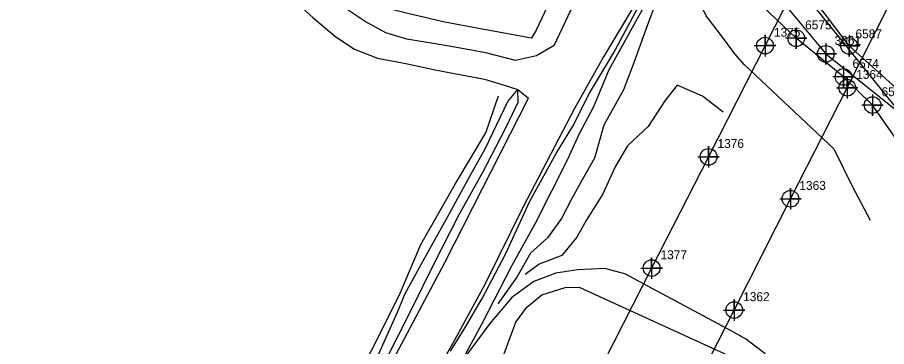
# Model space of a CAD drawing. Extents: x 2062781 to 2066835, y 358981 to 366501.
# Drawn here: x 2065489 to 2065733, y 364608.5 to 364700.9 of the extents above; entities that cross this region are included whole.
import ezdxf

# ---------------------------------------------------------------- set-up
doc = ezdxf.new("R2010")
doc.units = 0
for name, color, linetype in [('Exist DTM Breakline Underwater Cogo Number', 7, 'Continuous'), ('Exist DTM Drainline', 7, 'Continuous'), ('Exist DTM Regular Point Underwater Cogo Number', 7, 'Continuous'), ('Exist DTM Ridgeline', 7, 'Continuous'), ('Exist DTM Ridgeline Cogo Number', 7, 'Continuous'), ('Exist DTM Ridgeline Cogo Point CELL', 7, 'Continuous'), ('Exist Structure Major Deck Tunnel Box Culvert', 7, 'Continuous'), ('Exist Structure Major Deck Tunnel Box Culvert Cogo Number', 7, 'Continuous'), ('Exist Structure Major Deck Tunnel Box Culvert Cogo Point CELL', 7, 'Continuous'), ('PH Exist DTM Breakline', 7, 'Continuous'), ('PH Exist DTM Point', 7, 'Continuous')]:
    doc.layers.add(name, color=color, linetype=linetype)

msp = doc.modelspace()

# ---------------------------------------------------------------- linework, layer by layer
at = {"layer": 'Exist DTM Breakline Underwater Cogo Number'}
msp.add_lwpolyline([(2065715.94, 364693.69), (2065715.94, 364687.69), (2065715.94, 364690.69), (2065718.94, 364690.69), (2065712.94, 364690.69)], dxfattribs=at)
msp.add_lwpolyline([(2065715.94, 364693.69), (2065715.94, 364687.69), (2065715.94, 364690.69), (2065718.94, 364690.69), (2065712.94, 364690.69)], dxfattribs=at)
msp.add_lwpolyline([(2065715.94, 364693.69), (2065715.94, 364687.69), (2065715.94, 364690.69), (2065718.94, 364690.69), (2065712.94, 364690.69)], dxfattribs=at)
msp.add_circle((2065715.94, 364690.69), 2.34, dxfattribs=at)
msp.add_circle((2065715.94, 364690.69), 2.34, dxfattribs=at)
msp.add_circle((2065715.94, 364690.69), 2.34, dxfattribs=at)
at = {"layer": 'Exist DTM Drainline'}
for p in [(2065704.09, 364714.74), (2065715.94, 364690.69)]:
    msp.add_line(p, (2065736.94, 364673.9), dxfattribs=at)
msp.add_lwpolyline([(2065684.56, 364732.28), (2065688.06, 364722.81), (2065697.32, 364709.2), (2065704.32, 364704.74), (2065715.94, 364690.69)], dxfattribs=at)
at = {"layer": 'Exist DTM Ridgeline'}
for points in [[(2065756.36, 364640.41), (2065752.93, 364643.32), (2065750.15, 364650.41), (2065736.13, 364666.27), (2065729.12, 364676.31), (2065720.96, 364684.21), (2065707.66, 364695.07), (2065692.58, 364709.52), (2065685.05, 364722.21), (2065679.07, 364731.03), (2065683.91, 364739.54), (2065689.64, 364738.67), (2065696, 364731.44), (2065702.13, 364731.15), (2065704.47, 364727.59), (2065700.39, 364723.94)], [(2065722.51, 364692.9), (2065711.1, 364708.1), (2065707.56, 364711.6), (2065700.39, 364723.94)], [(2065722.51, 364692.9), (2065736.53, 364680.31), (2065745.83, 364668.65), (2065755.91, 364658.15), (2065762.12, 364648.29)]]:
    msp.add_lwpolyline(points, dxfattribs=at)
at = {"layer": 'Exist DTM Ridgeline Cogo Point CELL'}
for points in [[(2065707.66, 364698.07), (2065707.66, 364692.07), (2065707.66, 364695.07), (2065710.66, 364695.07), (2065704.66, 364695.07)], [(2065707.66, 364698.07), (2065707.66, 364692.07), (2065707.66, 364695.07), (2065710.66, 364695.07), (2065704.66, 364695.07)], [(2065707.66, 364698.07), (2065707.66, 364692.07), (2065707.66, 364695.07), (2065710.66, 364695.07), (2065704.66, 364695.07)], [(2065722.51, 364695.9), (2065722.51, 364689.9), (2065722.51, 364692.9), (2065725.51, 364692.9), (2065719.51, 364692.9)], [(2065722.51, 364695.9), (2065722.51, 364689.9), (2065722.51, 364692.9), (2065725.51, 364692.9), (2065719.51, 364692.9)], [(2065722.51, 364695.9), (2065722.51, 364689.9), (2065722.51, 364692.9), (2065725.51, 364692.9), (2065719.51, 364692.9)], [(2065720.96, 364687.21), (2065720.96, 364681.21), (2065720.96, 364684.21), (2065723.96, 364684.21), (2065717.96, 364684.21)], [(2065720.96, 364687.21), (2065720.96, 364681.21), (2065720.96, 364684.21), (2065723.96, 364684.21), (2065717.96, 364684.21)], [(2065720.96, 364687.21), (2065720.96, 364681.21), (2065720.96, 364684.21), (2065723.96, 364684.21), (2065717.96, 364684.21)], [(2065729.12, 364679.31), (2065729.12, 364673.31), (2065729.12, 364676.31), (2065732.12, 364676.31), (2065726.12, 364676.31)], [(2065729.12, 364679.31), (2065729.12, 364673.31), (2065729.12, 364676.31), (2065732.12, 364676.31), (2065726.12, 364676.31)], [(2065729.12, 364679.31), (2065729.12, 364673.31), (2065729.12, 364676.31), (2065732.12, 364676.31), (2065726.12, 364676.31)]]:
    msp.add_lwpolyline(points, dxfattribs=at)
for centre in [(2065707.66, 364695.07), (2065707.66, 364695.07), (2065707.66, 364695.07), (2065722.51, 364692.9), (2065722.51, 364692.9), (2065722.51, 364692.9), (2065720.96, 364684.21), (2065720.96, 364684.21), (2065720.96, 364684.21), (2065729.12, 364676.31), (2065729.12, 364676.31), (2065729.12, 364676.31)]:
    msp.add_circle(centre, 2.34, dxfattribs=at)
at = {"layer": 'Exist Structure Major Deck Tunnel Box Culvert'}
msp.add_lwpolyline([(2065674.29, 364587.57), (2065690.26, 364618.75), (2065706.04, 364650), (2065722, 364681.17), (2065737.82, 364712.48), (2065753.7, 364743.62), (2065769.52, 364774.84), (2065785.48, 364805.99), (2065801.23, 364837.35), (2065778.26, 364849.13), (2065762.32, 364817.83), (2065746.45, 364786.64), (2065730.62, 364755.39), (2065714.76, 364724.23), (2065698.9, 364692.99), (2065683.06, 364661.76), (2065667.07, 364630.54), (2065651.24, 364599.44), (2065674.29, 364587.57)], dxfattribs=at)
at = {"layer": 'Exist Structure Major Deck Tunnel Box Culvert Cogo Point CELL'}
for points in [[(2065695.9, 364692.99), (2065701.9, 364692.99), (2065698.9, 364692.99), (2065698.9, 364695.99), (2065698.9, 364689.99)], [(2065695.9, 364692.99), (2065701.9, 364692.99), (2065698.9, 364692.99), (2065698.9, 364695.99), (2065698.9, 364689.99)], [(2065695.9, 364692.99), (2065701.9, 364692.99), (2065698.9, 364692.99), (2065698.9, 364695.99), (2065698.9, 364689.99)], [(2065719, 364681.17), (2065725, 364681.17), (2065722, 364681.17), (2065722, 364684.17), (2065722, 364678.17)], [(2065719, 364681.17), (2065725, 364681.17), (2065722, 364681.17), (2065722, 364684.17), (2065722, 364678.17)], [(2065719, 364681.17), (2065725, 364681.17), (2065722, 364681.17), (2065722, 364684.17), (2065722, 364678.17)], [(2065680.06, 364661.76), (2065686.06, 364661.76), (2065683.06, 364661.76), (2065683.06, 364664.76), (2065683.06, 364658.76)], [(2065680.06, 364661.76), (2065686.06, 364661.76), (2065683.06, 364661.76), (2065683.06, 364664.76), (2065683.06, 364658.76)], [(2065680.06, 364661.76), (2065686.06, 364661.76), (2065683.06, 364661.76), (2065683.06, 364664.76), (2065683.06, 364658.76)], [(2065703.04, 364650), (2065709.04, 364650), (2065706.04, 364650), (2065706.04, 364653), (2065706.04, 364647)], [(2065703.04, 364650), (2065709.04, 364650), (2065706.04, 364650), (2065706.04, 364653), (2065706.04, 364647)], [(2065703.04, 364650), (2065709.04, 364650), (2065706.04, 364650), (2065706.04, 364653), (2065706.04, 364647)], [(2065664.07, 364630.54), (2065670.07, 364630.54), (2065667.07, 364630.54), (2065667.07, 364633.54), (2065667.07, 364627.54)], [(2065664.07, 364630.54), (2065670.07, 364630.54), (2065667.07, 364630.54), (2065667.07, 364633.54), (2065667.07, 364627.54)], [(2065664.07, 364630.54), (2065670.07, 364630.54), (2065667.07, 364630.54), (2065667.07, 364633.54), (2065667.07, 364627.54)], [(2065687.26, 364618.75), (2065693.26, 364618.75), (2065690.26, 364618.75), (2065690.26, 364621.75), (2065690.26, 364615.75)], [(2065687.26, 364618.75), (2065693.26, 364618.75), (2065690.26, 364618.75), (2065690.26, 364621.75), (2065690.26, 364615.75)], [(2065687.26, 364618.75), (2065693.26, 364618.75), (2065690.26, 364618.75), (2065690.26, 364621.75), (2065690.26, 364615.75)]]:
    msp.add_lwpolyline(points, dxfattribs=at)
for centre in [(2065698.9, 364692.99), (2065698.9, 364692.99), (2065698.9, 364692.99), (2065722, 364681.17), (2065722, 364681.17), (2065722, 364681.17), (2065683.06, 364661.76), (2065683.06, 364661.76), (2065683.06, 364661.76), (2065706.04, 364650), (2065706.04, 364650), (2065706.04, 364650), (2065667.07, 364630.54), (2065667.07, 364630.54), (2065667.07, 364630.54), (2065690.26, 364618.75), (2065690.26, 364618.75), (2065690.26, 364618.75)]:
    msp.add_circle(centre, 2.34, dxfattribs=at)
at = {"layer": 'PH Exist DTM Breakline'}
for points in [[(2065660.05, 364747.21), (2065652.74, 364733.94), (2065647.3, 364724.19), (2065634.61, 364697.38), (2065633.33, 364695.06), (2065619.03, 364697.74), (2065609.03, 364699.54), (2065598.94, 364701.96), (2065587.11, 364704.96), (2065580.61, 364708.55), (2065571.79, 364715.59), (2065559.5, 364725.9), (2065541.44, 364743.3), (2065532.03, 364751.24), (2065520.5, 364760.95), (2065511.71, 364768.87), (2065500.52, 364779), (2065493.11, 364785.37), (2065487.24, 364790.19), (2065477.93, 364797.52), (2065465.26, 364806.84), (2065452.16, 364818.79)], [(2065639.68, 364693), (2065634.69, 364690.12), (2065628.85, 364688.84), (2065620.9, 364690.85), (2065617.44, 364691.57), (2065610.73, 364692.79), (2065598.28, 364694.84), (2065592.41, 364696.62), (2065586.64, 364699.8), (2065575.14, 364707.52), (2065561.85, 364718.71), (2065546.86, 364732.09), (2065527.94, 364749.68), (2065508.21, 364767.32), (2065489.17, 364783.14), (2065470.41, 364798.67), (2065451.42, 364814.97)], [(2065447.48, 364808.89), (2065476.57, 364784.85), (2065501.56, 364763.78), (2065522.61, 364745.31), (2065540.38, 364728.8), (2065555.41, 364715.91), (2065571.89, 364700.89), (2065578.36, 364695.51), (2065583.64, 364691.99), (2065590.04, 364689.44), (2065598.02, 364687.96), (2065606.75, 364686.07), (2065620.11, 364683.54), (2065625.38, 364681.99), (2065629.46, 364680.72), (2065632.47, 364678.22)], [(2065639.68, 364693), (2065645.18, 364704.75), (2065652.35, 364720.03), (2065665.17, 364744.65), (2065672.12, 364758.01)], [(2065678.72, 364737.58), (2065673.92, 364728.12), (2065662.86, 364705.32), (2065653.55, 364689.83), (2065645.39, 364675.34), (2065631.03, 364647.71), (2065620.21, 364625.92), (2065611.7, 364610.32), (2065595.23, 364580.8), (2065582.27, 364556.74), (2065569.58, 364532.46), (2065556.01, 364505), (2065544.12, 364483.42), (2065531.2, 364457.8), (2065510.87, 364417.22)], [(2065607.43, 364592.58), (2065619.53, 364615.14), (2065627.85, 364631.19), (2065634.56, 364643.36), (2065639.06, 364652.2), (2065643.5, 364661.13), (2065646.79, 364668.31), (2065650.82, 364675.86), (2065655.1, 364686.31), (2065662.58, 364699.73), (2065667.38, 364708.44), (2065672.49, 364717.25), (2065676.42, 364724.68), (2065678.83, 364732.84), (2065681.69, 364738.16)], [(2065610.61, 364607.21), (2065614.74, 364613.82), (2065619.52, 364621.99), (2065626.04, 364634.45), (2065632.89, 364649.32), (2065640.27, 364662.72), (2065644.92, 364670.37), (2065649.57, 364679.66), (2065656.39, 364690.91), (2065663.76, 364704.67), (2065669.38, 364716.75), (2065676.03, 364731.11)], [(2065682.55, 364718.92), (2065679.23, 364719.59), (2065676.39, 364718.86), (2065671.46, 364713.43), (2065666.56, 364700.6), (2065661.62, 364686.98), (2065659.17, 364680.62), (2065653.6, 364670.71), (2065650.99, 364661.36), (2065647.53, 364655.3), (2065644.64, 364650.05), (2065641.77, 364644.5), (2065637.8, 364638.99), (2065633.05, 364634.7), (2065629.18, 364627.96), (2065623.86, 364620.46)], [(2065693.11, 364687.64), (2065690.46, 364690.67), (2065686.39, 364696.12), (2065682.4, 364701.37), (2065680.81, 364704.7), (2065680.33, 364709.43), (2065682.33, 364712.65), (2065685.11, 364716.44), (2065685.71, 364717.4)], [(2065693.11, 364687.64), (2065718.21, 364664.02), (2065723.25, 364653.77), (2065728.42, 364644.03)], [(2065687.14, 364674.36), (2065681.34, 364678.82), (2065674.22, 364681.93), (2065670.76, 364677.47), (2065666.05, 364670.3), (2065660.33, 364664.83), (2065656.93, 364659.14), (2065653.23, 364651.17), (2065648.64, 364643.86), (2065646.09, 364639.23), (2065641.86, 364634.08), (2065635.49, 364631.65), (2065631.56, 364628.7)], [(2065492.71, 364424.31), (2065496.87, 364431.96), (2065498.77, 364435.71), (2065500.67, 364439.92), (2065502.4, 364444.35), (2065504.63, 364450.5), (2065515.15, 364470.32), (2065519.97, 364479.97), (2065531.43, 364501.79), (2065534.8, 364507.56), (2065542.75, 364522.28), (2065554.49, 364542.54), (2065563.87, 364562.18), (2065573.16, 364579.62), (2065578.82, 364589.36), (2065584.37, 364599.43), (2065592.47, 364615.39), (2065596.41, 364623.51), (2065602.25, 364637.12), (2065611.92, 364654.13), (2065620.46, 364668.53), (2065624.1, 364678.86)], [(2065498.04, 364422.28), (2065502.5, 364431.06), (2065507.65, 364441.4), (2065513.57, 364452.15), (2065521.09, 364466.72), (2065525.81, 364476.58), (2065532.21, 364489.15), (2065538.77, 364502.06), (2065544.55, 364514.07), (2065550.04, 364523.99), (2065558.03, 364539.96), (2065564.65, 364552.55), (2065571.07, 364565.07), (2065578.1, 364579.19), (2065584.54, 364590.87), (2065592.05, 364603.95), (2065599.95, 364619.48), (2065605.77, 364631.48), (2065612.98, 364645.55), (2065619.68, 364657.45), (2065625.94, 364669.56), (2065629.59, 364677.1), (2065629.46, 364680.72)], [(2065590.37, 364606.27), (2065595.72, 364618.14), (2065597.88, 364623.42), (2065604.87, 364636.14), (2065609.79, 364645.05), (2065615.94, 364656.19), (2065620.36, 364664.02), (2065626.71, 364677.29), (2065629.46, 364680.72)], [(2065500.23, 364422.77), (2065518.41, 364458.3), (2065536.53, 364493.34), (2065552.06, 364523.36), (2065570.83, 364559.81), (2065588.8, 364594.04), (2065609.03, 364632.08), (2065624.74, 364662.98), (2065632.47, 364678.22)], [(2065704.96, 364572.17), (2065706.13, 364576.85), (2065707.18, 364584.29), (2065706.26, 364592.47), (2065703.74, 364599.03), (2065698.84, 364606.58), (2065693.4, 364610.71), (2065689.35, 364612.94), (2065659.55, 364628.88), (2065653.93, 364630.4), (2065646.2, 364630.02), (2065640.16, 364629.11), (2065634, 364626.73), (2065627.77, 364622.24), (2065621.61, 364614.94), (2065613.9, 364604.53), (2065607.43, 364592.58), (2065601.04, 364580.17), (2065592.64, 364564.15), (2065580.5, 364541.95)], [(2065619.19, 364584.28), (2065617.22, 364586.76), (2065621.27, 364595.82), (2065625.76, 364606.72), (2065628.91, 364615.32), (2065631.99, 364619.55), (2065636.19, 364623.04), (2065642.8, 364625.11), (2065646.67, 364625.16), (2065690.68, 364605.03), (2065695.53, 364601.16), (2065699.52, 364596.46), (2065702.16, 364591.83), (2065704.05, 364585.32), (2065702.96, 364580.98), (2065699.3, 364576.19), (2065691.44, 364571.02), (2065685.54, 364569.28), (2065679.52, 364572.22)]]:
    msp.add_lwpolyline(points, dxfattribs=at)
at = {"layer": 'PH Exist DTM Point'}
for p, q in [((2065555.21, 364691.06), (2065555.21, 364691.06)), ((2065497.6, 364688.23), (2065497.6, 364688.23)), ((2065520.47, 364688.55), (2065520.47, 364688.55)), ((2065538.66, 364688.19), (2065538.66, 364688.19)), ((2065679.81, 364688.52), (2065679.81, 364688.52)), ((2065575.98, 364679.49), (2065575.98, 364679.49)), ((2065614.93, 364674.21), (2065614.93, 364674.21)), ((2065637.7, 364674.78), (2065637.7, 364674.78)), ((2065518.39, 364670.78), (2065518.39, 364670.78)), ((2065600.53, 364668.93), (2065600.53, 364668.93)), ((2065720.87, 364669.56), (2065720.87, 364669.56)), ((2065494.98, 364667.68), (2065494.98, 364667.68)), ((2065559.33, 364668.02), (2065559.33, 364668.02)), ((2065539.2, 364665.13), (2065539.2, 364665.13)), ((2065577.16, 364665.73), (2065577.16, 364665.73)), ((2065677.97, 364665.73), (2065677.97, 364665.73)), ((2065522.4, 364653.53), (2065522.4, 364653.53)), ((2065500.94, 364649.01), (2065500.94, 364649.01)), ((2065559.94, 364649.34), (2065559.94, 364649.34)), ((2065576.32, 364649.66), (2065576.32, 364649.66)), ((2065540.54, 364648.8), (2065540.54, 364648.8)), ((2065600.33, 364648.42), (2065600.33, 364648.42)), ((2065659.57, 364648.66), (2065659.57, 364648.66)), ((2065719.19, 364647.97), (2065719.19, 364647.97)), ((2065705.76, 364641.42), (2065705.76, 364641.42)), ((2065592.47, 364630.3), (2065592.47, 364630.3)), ((2065614.04, 364631.7), (2065614.04, 364631.7)), ((2065660.74, 364631.4), (2065660.74, 364631.4)), ((2065497.78, 364629.18), (2065497.78, 364629.18)), ((2065519.26, 364628.07), (2065519.26, 364628.07)), ((2065540.26, 364628.28), (2065540.26, 364628.28)), ((2065559.59, 364628.76), (2065559.59, 364628.76)), ((2065578.88, 364627.58), (2065578.88, 364627.58)), ((2065700.28, 364628.04), (2065700.28, 364628.04)), ((2065719.57, 364628.66), (2065719.57, 364628.66)), ((2065648.2, 364615.99), (2065648.2, 364615.99)), ((2065635.15, 364613.77), (2065635.15, 364613.77)), ((2065499.35, 364608.7), (2065499.35, 364608.7)), ((2065519.25, 364609.3), (2065519.25, 364609.3)), ((2065559.66, 364608.85), (2065559.66, 364608.85)), ((2065639.55, 364608.66), (2065639.55, 364608.66)), ((2065699.57, 364608.66), (2065699.57, 364608.66))]:
    msp.add_line(p, q, dxfattribs=at)

# ---------------------------------------------------------------- texts
at = {"layer": 'Exist DTM Regular Point Underwater Cogo Number'}
msp.add_text('3061', height=2.5, dxfattribs=at).set_placement((2065718.44, 364693.19))
msp.add_text('3061', height=2.5, dxfattribs=at).set_placement((2065718.44, 364693.19))
msp.add_text('3061', height=2.5, dxfattribs=at).set_placement((2065718.44, 364693.19))
at = {"layer": 'Exist DTM Ridgeline Cogo Number'}
for s, p in [('6575', (2065710.16, 364697.57)), ('6575', (2065710.16, 364697.57)), ('6575', (2065710.16, 364697.57)), ('6587', (2065724.3, 364695.05)), ('6587', (2065724.3, 364695.05)), ('6587', (2065724.3, 364695.05)), ('6574', (2065723.46, 364686.71)), ('6574', (2065723.46, 364686.71)), ('6574', (2065723.46, 364686.71)), ('6573', (2065731.62, 364678.81)), ('6573', (2065731.62, 364678.81)), ('6573', (2065731.62, 364678.81))]:
    msp.add_text(s, height=2.5, dxfattribs=at).set_placement(p)
at = {"layer": 'Exist Structure Major Deck Tunnel Box Culvert Cogo Number'}
for s, p in [('1375', (2065701.4, 364695.49)), ('1375', (2065701.4, 364695.49)), ('1375', (2065701.4, 364695.49)), ('1364', (2065724.5, 364683.67)), ('1364', (2065724.5, 364683.67)), ('1364', (2065724.5, 364683.67)), ('1376', (2065685.56, 364664.26)), ('1376', (2065685.56, 364664.26)), ('1376', (2065685.56, 364664.26)), ('1363', (2065708.54, 364652.5)), ('1363', (2065708.54, 364652.5)), ('1363', (2065708.54, 364652.5)), ('1377', (2065669.57, 364633.04)), ('1377', (2065669.57, 364633.04)), ('1377', (2065669.57, 364633.04)), ('1362', (2065692.76, 364621.25)), ('1362', (2065692.76, 364621.25)), ('1362', (2065692.76, 364621.25))]:
    msp.add_text(s, height=2.5, dxfattribs=at).set_placement(p)

doc.saveas('drawing.dxf')
